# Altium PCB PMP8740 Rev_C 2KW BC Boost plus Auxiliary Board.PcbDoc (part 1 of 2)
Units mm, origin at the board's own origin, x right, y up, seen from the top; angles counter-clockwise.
Board outline 261.75 x 149.86 mm, 2 copper layers (Top Layer, Bottom Layer), stack 1.575 mm thick; 147 components, 79 nets, 365 pads, 168 vias.
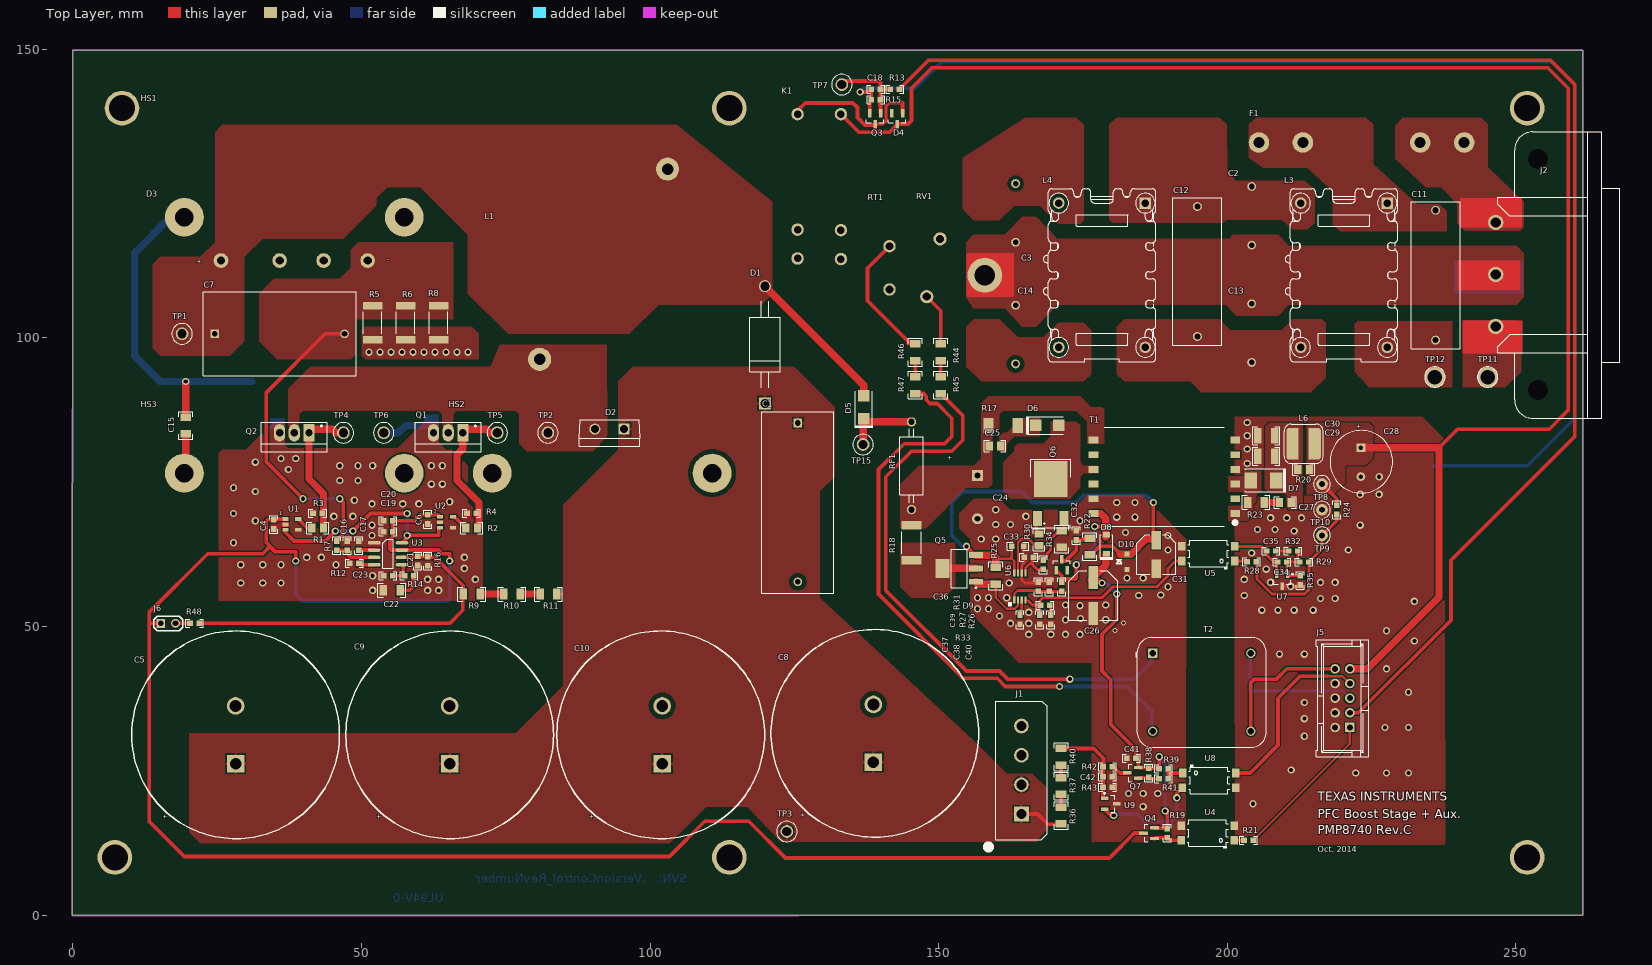
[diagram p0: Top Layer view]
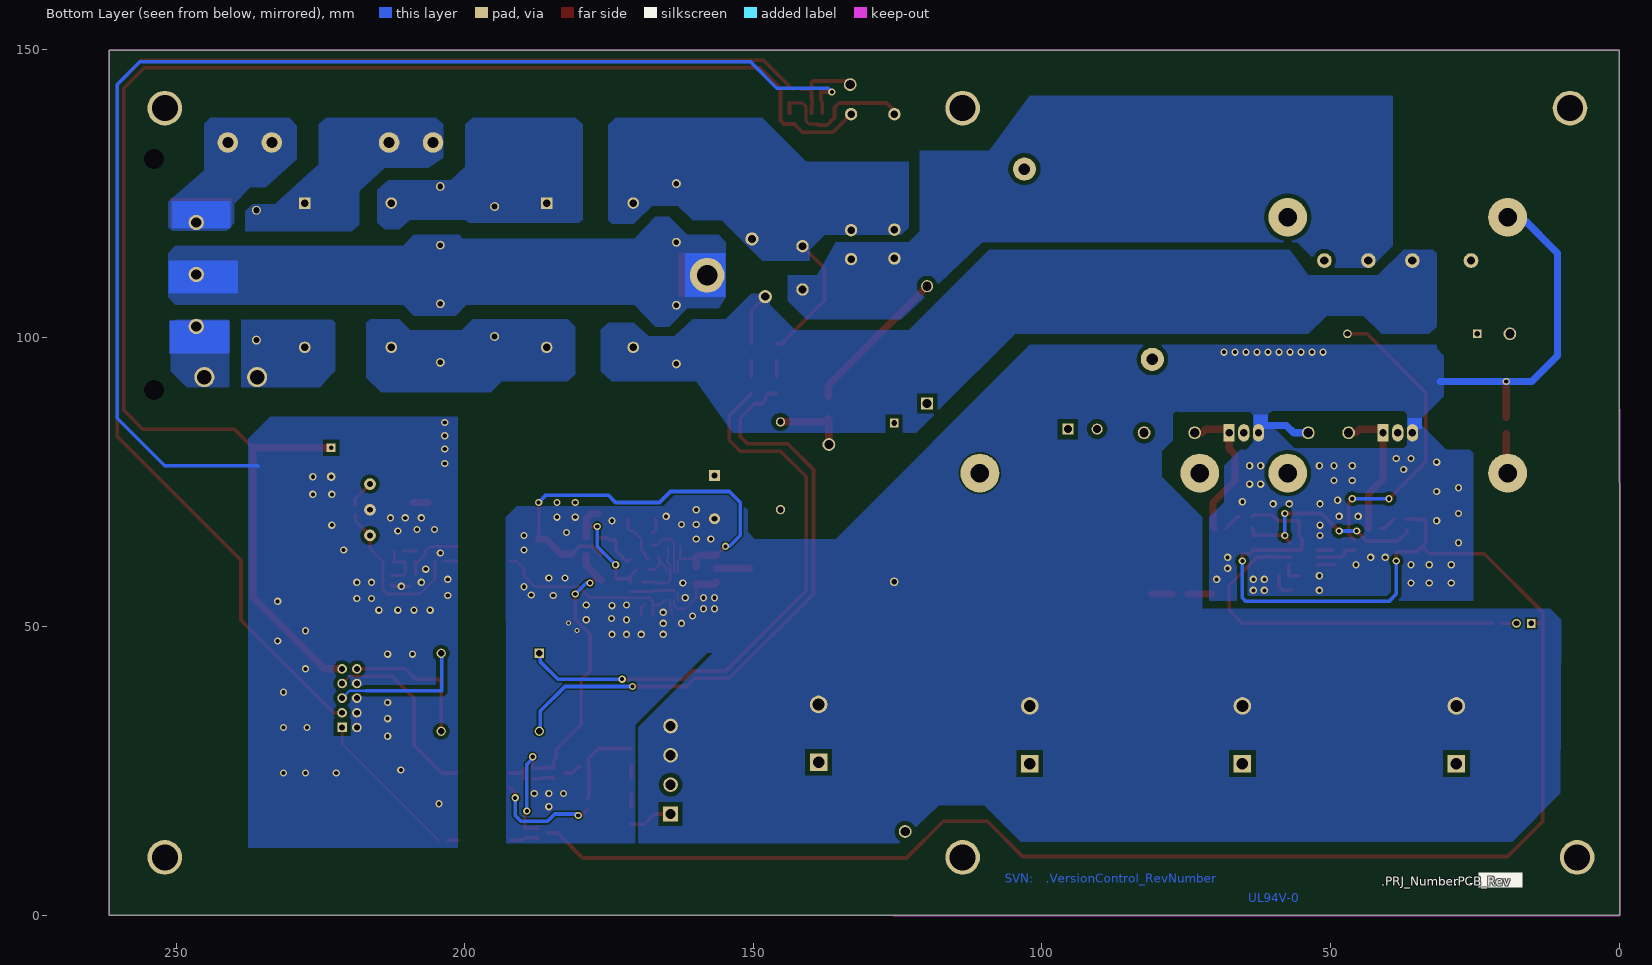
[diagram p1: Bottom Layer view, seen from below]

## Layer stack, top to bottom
Top Layer: signal copper 0.0356
Dielectric: core 1.5037, FR-4, Dk 4.8
Bottom Layer: signal copper 0.0356

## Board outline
-0.127,0 261.62,0 261.62,149.86 0,149.86

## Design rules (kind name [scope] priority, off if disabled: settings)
AcuteAngle [All] p1: minimum=4.50000000000000E+0001 checktracksonly=FALSE
AssemblyTestPointUsage [All] p1: valid=2
Clearance "Schematic Clearance Constraint_3" [InNet('NetD3_3')] p1: gap=0.762
Clearance "Schematic Clearance Constraint_2" [InNet('AC1')] p2: gap=0.762
Clearance Clearance_16 [InNamedPolygon('Bottom Layer-No Net 7')] p3: gap=0.254
Clearance "Schematic Clearance Constraint_1" [InNet('NetHS2_2')] p4: gap=0.762
Clearance "Schematic Clearance Constraint" [InNet('NetD2_2')] p5: gap=0.762
Clearance Clearance_15 [InNamedPolygon('Bottom Layer-No Net 7')] p6: gap=0.305
Clearance Clearance_14 [InNamedPolygon('Bottom Layer-No Net 9')] p7: gap=0.254
Clearance Clearance_13 [InNamedPolygon('Bottom Layer-No Net 9')] p8: gap=0.254
Clearance Clearance_12 [InNet('+390V')] p9: gap=0.762
Clearance Clearance_11 [InNamedPolygon('Top Layer-No Net 5')] p10: gap=0.762
Clearance Clearance_10 [InNamedPolygon('Top Layer-No Net 5')] p11: gap=0.762
Clearance Clearance_9 [InNamedPolygon('Top Layer-No Net 5')] p12: gap=0.508
Clearance Clearance_8 [InNamedPolygon('Top Layer-No Net 5')] p13: gap=0.508
Clearance Clearance_7 [InNamedPolygon('Top Layer-No Net 5')] p14: gap=0.508
Clearance Clearance_6 [InNamedPolygon('Bottom Layer-No Net 8')] p15: gap=0.254
Clearance Clearance_5 [InNamedPolygon('Top Layer-No Net 10')] p16: gap=0.254
Clearance Clearance_4 [InNamedPolygon('Top Layer-No Net 5')] p17: gap=0.762
Clearance Clearance_3 [InNamedPolygon('Bottom Layer-No Net 7')] p18: gap=0.254
Clearance Clearance_2 [InNamedPolygon('Bottom Layer-No Net 7')] p19: gap=0.254
Clearance Clearance_1 [InNamedPolygon('Top Layer-No Net 3')] p20: gap=0.254
Clearance Clearance_BoardEdge_MountingHoles [OnCopper and InComponentClass('Mounting Holes') vs IsKeepOut] p21: gap=1.016
Clearance Clearance_BoardEdge_Poly [OnCopper and InPoly vs IsKeepOut] p22: gap=0.635
Clearance Clearance_BoardEdge [OnCopper and Not InComponentClass('Logo') and not InComponentClass('FiducialMark') and not InRegion(1000,500,4000,800) and Not IsKeepout vs IsKeepOut] p23: gap=0.635
Clearance Clearance_Poly [InPolygon] p24: gap=0.635
Clearance [All] p25: gap=0.229
ComponentClearance ComponentClearance_Logo [InComponentClass('Logo')] p1: gap=1.27 collisioncheckmode=3 verticalgap=0.254 showdistances=FALSE
ComponentClearance ComponentClearance_ScrewToNut [(HasFootprint('NY PMS 440 0025 PH')) vs (HasFootprint('Keystone_1902C'))] p2: gap=0.127 collisioncheckmode=3 verticalgap=0.254 showdistances=FALSE
ComponentClearance ComponentClearance_MountingHoles [InComponentClass('Mounting Holes')] p3: gap=6.35 collisioncheckmode=3 verticalgap=2540 showdistances=FALSE
ComponentClearance ComponentClearance_SmallPassives [HasFootprint('0201*') or HasFootprint('0402*') or HasFootprint('0508') or HasFootprint('0603*') or HasFootprint('0612') or HasFootprint('0805*') or HasFootprint('0815*') or HasFootprint('0830*') or HasFootprint('1206*') or HasFootprint('1210*') or HasFootprint('1808*') or HasFootprint('1812*') or HasFootprint('1825*') or HasFootprint('2010*') or HasFootprint('2220*') or HasFootprint('2225*') or HasFootprint('2512*') or HasFootprint('2728*') or HasFootprint('3518*') vs HasFootprint('0201*') or HasFootprint('0402*') or HasFootprint('0508') or HasFootprint('0603*') or HasFootprint('0612') or HasFootprint('0805*') or HasFootprint('0815*') or HasFootprint('0830*') or HasFootprint('1206*') or HasFootprint('1210*') or HasFootprint('1808*') or HasFootprint('1812*') or HasFootprint('1825*') or HasFootprint('2010*') or HasFootprint('2220*') or HasFootprint('2225*') or HasFootprint('2512*') or HasFootprint('2728*') or HasFootprint('3518*')] p4: gap=0.508 collisioncheckmode=3 verticalgap=0.254 showdistances=FALSE
ComponentClearance ComponentClearance_THtoSMT [IsThruComponent vs IsSMTComponent] p5: gap=0.508 collisioncheckmode=3 verticalgap=0.762 showdistances=FALSE
ComponentClearance ComponentClearance_THtoTH [IsThruComponent vs IsThruComponent] p6: gap=3 collisioncheckmode=3 verticalgap=0.762 showdistances=FALSE
ComponentClearance [All] p7: gap=0.508 collisioncheckmode=3 verticalgap=2540 showdistances=FALSE
DiffPairsRouting [All] p1: maxlimit=2.54 minlimit=0.254 mostfreqgap=0.254 maxuncoupledlength=25.4
FabricationTestPointUsage TestPointUsage [All] p1: valid=2 allowmultiple=FALSE
FabricationTestpoint Testpoint [All] p1: side=3 testpointundercomponent=TRUE minsize=1.016 maxsize=2.54 preferedsize=1.524 minholesize=0 maxholesize=1.016 preferedholesize=0.813 testpointgrid=0.025 allowsidetop=TRUE allowsidebottom=TRUE usegrid=TRUE gridtolerance=0
FanoutControl Fanout_LCC [IsLCC] p1: bgadir=Out bgaviamode=Centered fanoutstyle=Auto fanoutdirection=Alternating viagrid=0.025 // Fanout_LCC (Default Rule)
FanoutControl Fanout_BGA [IsBGA] p2: bgadir=Out bgaviamode=Centered fanoutstyle=Auto fanoutdirection=Alternating viagrid=0.025 // Fanout_BGA (Default Rule)
FanoutControl Fanout_Default [All] p4: bgadir=Out bgaviamode=Centered fanoutstyle=Auto fanoutdirection=Alternating viagrid=0.025 // Fanout_Default (Default Rule)
FanoutControl Fanout_Small [(CompPinCount < 5)] p5: bgadir=Out bgaviamode=Centered fanoutstyle=Auto fanoutdirection=OutThenIn viagrid=0.025 // Fanout_Small (Default Rule)
Height [All] p1: minheight=0 maxheight=45 prefheight=12.7
HoleSize [All] p1: absolutevalues=TRUE maxlimit=6.375 minlimit=0.203 maxpercent=80.000 minpercent=20.000
MinimumAnnularRing MinimumAnnularRing_ThermalPadVias [IsVia and InAnyComponent] p1: minimumring=0.15
MinimumAnnularRing [All] p2: minimumring=0.229
MinimumSolderMaskSliver MinimumSolderMaskSliver_Logo [InComponentClass('Logo') vs InComponentClass('Logo')] p1: minsoldermaskwidth=0.018
MinimumSolderMaskSliver [All] p2: minsoldermaskwidth=0.1
PlaneConnect [All] p1: planeconnectstyle=Relief reliefexpansion=0.254 reliefentries=4 reliefconductorwidth=0.254 reliefairgap=0.254
PolygonConnect PolygonConnect_37 [All vs IsNamedPolygon('Bottom Layer-No Net 11')] p1: connectstyle=Direct reliefconductorwidth=0.254 reliefentries=4 polygonreliefangle="90 Angle" airgapwidth=0.254
PolygonConnect PolygonConnect_36 [All vs IsNamedPolygon('Bottom Layer-No Net 11')] p2: connectstyle=Direct reliefconductorwidth=0.254 reliefentries=4 polygonreliefangle="90 Angle" airgapwidth=0.254
PolygonConnect PolygonConnect_35 [All vs IsNamedPolygon('Top Layer-No Net 1')] p3: connectstyle=Direct reliefconductorwidth=0.254 reliefentries=4 polygonreliefangle="90 Angle" airgapwidth=0.254
PolygonConnect PolygonConnect_34 [All vs IsNamedPolygon('Top Layer-No Net 1')] p4: connectstyle=Direct reliefconductorwidth=0.254 reliefentries=4 polygonreliefangle="90 Angle" airgapwidth=0.254
PolygonConnect PolygonConnect_33 [All vs IsNamedPolygon('Bottom Layer-No Net 10')] p5: connectstyle=Direct reliefconductorwidth=0.254 reliefentries=4 polygonreliefangle="90 Angle" airgapwidth=0.254
PolygonConnect PolygonConnect_32 [All vs IsNamedPolygon('Bottom Layer-No Net 4')] p6: connectstyle=Direct reliefconductorwidth=0.254 reliefentries=4 polygonreliefangle="90 Angle" airgapwidth=0.254
PolygonConnect PolygonConnect_31 [All vs IsNamedPolygon('Bottom Layer-No Net 9')] p7: connectstyle=Direct reliefconductorwidth=0.254 reliefentries=4 polygonreliefangle="90 Angle" airgapwidth=0.254
PolygonConnect PolygonConnect_30 [All vs IsNamedPolygon('Top Layer-No Net 13')] p8: connectstyle=Direct reliefconductorwidth=0.254 reliefentries=4 polygonreliefangle="90 Angle" airgapwidth=0.254
PolygonConnect PolygonConnect_29 [All vs IsNamedPolygon('Top Layer-No Net 12')] p9: connectstyle=Direct reliefconductorwidth=0.254 reliefentries=4 polygonreliefangle="90 Angle" airgapwidth=0.254
PolygonConnect PolygonConnect_28 [All vs IsNamedPolygon('Top Layer-No Net 11')] p10: connectstyle=Direct reliefconductorwidth=0.254 reliefentries=4 polygonreliefangle="90 Angle" airgapwidth=0.254
PolygonConnect PolygonConnect_27 [All vs IsNamedPolygon('Bottom Layer-No Net 8')] p11: connectstyle=Direct reliefconductorwidth=0.254 reliefentries=4 polygonreliefangle="90 Angle" airgapwidth=0.254
PolygonConnect PolygonConnect_26 [All vs IsNamedPolygon('Top Layer-No Net 10')] p12: connectstyle=Direct reliefconductorwidth=0.254 reliefentries=4 polygonreliefangle="90 Angle" airgapwidth=0.254
PolygonConnect PolygonConnect_25 [All vs IsNamedPolygon('Top Layer-No Net 9')] p13: connectstyle=Direct reliefconductorwidth=0.254 reliefentries=4 polygonreliefangle="90 Angle" airgapwidth=0.254
PolygonConnect PolygonConnect_24 [All vs IsNamedPolygon('Top Layer-No Net 8')] p14: connectstyle=Direct reliefconductorwidth=0.254 reliefentries=4 polygonreliefangle="90 Angle" airgapwidth=0.254
PolygonConnect PolygonConnect_23 [All vs IsNamedPolygon('Top Layer-No Net 3')] p15: connectstyle=Direct reliefconductorwidth=0.254 reliefentries=4 polygonreliefangle="90 Angle" airgapwidth=0.254
PolygonConnect PolygonConnect_22 [All vs IsNamedPolygon('M5 Assembly Top-No Net')] p16: connectstyle=Direct reliefconductorwidth=0.254 reliefentries=4 polygonreliefangle="90 Angle" airgapwidth=0.254
PolygonConnect PolygonConnect_21 [All vs IsNamedPolygon('Top Layer-No Net 5')] p17: connectstyle=Relief reliefconductorwidth=0.508 reliefentries=4 polygonreliefangle="90 Angle" airgapwidth=0.254
PolygonConnect PolygonConnect_20 [All vs IsNamedPolygon('Top Layer-No Net 7')] p18: connectstyle=Direct reliefconductorwidth=0.254 reliefentries=4 polygonreliefangle="90 Angle" airgapwidth=0.254
PolygonConnect PolygonConnect_19 [All vs IsNamedPolygon('Top Layer-No Net 6')] p19: connectstyle=Direct reliefconductorwidth=0.254 reliefentries=4 polygonreliefangle="90 Angle" airgapwidth=0.254
PolygonConnect PolygonConnect_18 [All vs IsNamedPolygon('Bottom Layer-No Net 8')] p20: connectstyle=Relief reliefconductorwidth=0.508 reliefentries=4 polygonreliefangle="90 Angle" airgapwidth=0.254
PolygonConnect PolygonConnect_17 [All vs IsNamedPolygon('Top Layer-No Net 4')] p21: connectstyle=Direct reliefconductorwidth=0.254 reliefentries=4 polygonreliefangle="90 Angle" airgapwidth=0.254
PolygonConnect PolygonConnect_16 [All vs IsNamedPolygon('Bottom Layer-No Net 7')] p22: connectstyle=Direct reliefconductorwidth=0.254 reliefentries=4 polygonreliefangle="90 Angle" airgapwidth=0.254
PolygonConnect PolygonConnect_15 [All vs IsNamedPolygon('Top Layer-No Net 3')] p23: connectstyle=Direct reliefconductorwidth=0.254 reliefentries=4 polygonreliefangle="90 Angle" airgapwidth=0.254
PolygonConnect PolygonConnect_14 [All vs IsNamedPolygon('Bottom Layer-No Net 7')] p24: connectstyle=Direct reliefconductorwidth=0.254 reliefentries=4 polygonreliefangle="90 Angle" airgapwidth=0.254
PolygonConnect PolygonConnect_13 [All vs IsNamedPolygon('Bottom Layer-No Net 6')] p25: connectstyle=Direct reliefconductorwidth=0.254 reliefentries=4 polygonreliefangle="90 Angle" airgapwidth=0.254
PolygonConnect PolygonConnect_12 [All vs IsNamedPolygon('Bottom Layer-No Net 6')] p26: connectstyle=Direct reliefconductorwidth=0.254 reliefentries=4 polygonreliefangle="90 Angle" airgapwidth=0.254
PolygonConnect PolygonConnect_11 [All vs IsNamedPolygon('M1 Board Outline-No Net 1')] p27: connectstyle=Direct reliefconductorwidth=0.254 reliefentries=4 polygonreliefangle="90 Angle" airgapwidth=0.254
PolygonConnect PolygonConnect_10 [All vs IsNamedPolygon('M1 Board Outline-No Net 1')] p28: connectstyle=Direct reliefconductorwidth=0.254 reliefentries=4 polygonreliefangle="90 Angle" airgapwidth=0.254
PolygonConnect PolygonConnect_9 [All vs IsNamedPolygon('M1 Board Outline-No Net')] p29: connectstyle=Direct reliefconductorwidth=0.254 reliefentries=4 polygonreliefangle="90 Angle" airgapwidth=0.254
PolygonConnect PolygonConnect_8 [All vs IsNamedPolygon('Bottom Layer-No Net 5')] p30: connectstyle=Direct reliefconductorwidth=0.254 reliefentries=4 polygonreliefangle="90 Angle" airgapwidth=0.254
PolygonConnect PolygonConnect_7 [All vs IsNamedPolygon('Bottom Layer-No Net 4')] p31: connectstyle=Direct reliefconductorwidth=0.254 reliefentries=4 polygonreliefangle="90 Angle" airgapwidth=0.254
PolygonConnect PolygonConnect_6 [All vs IsNamedPolygon('Bottom Layer-No Net 3')] p32: connectstyle=Direct reliefconductorwidth=0.254 reliefentries=4 polygonreliefangle="90 Angle" airgapwidth=0.254
PolygonConnect PolygonConnect_5 [All vs IsNamedPolygon('Top Layer-No Net 2')] p33: connectstyle=Direct reliefconductorwidth=0.254 reliefentries=4 polygonreliefangle="90 Angle" airgapwidth=0.254
PolygonConnect PolygonConnect_4 [All vs IsNamedPolygon('Bottom Layer-No Net 2')] p34: connectstyle=Direct reliefconductorwidth=0.254 reliefentries=4 polygonreliefangle="90 Angle" airgapwidth=0.254
PolygonConnect PolygonConnect_3 [All vs IsNamedPolygon('Bottom Layer-No Net 1')] p35: connectstyle=Direct reliefconductorwidth=0.254 reliefentries=4 polygonreliefangle="90 Angle" airgapwidth=0.254
PolygonConnect PolygonConnect_2 [All vs IsNamedPolygon('Bottom Layer-No Net')] p36: connectstyle=Direct reliefconductorwidth=0.254 reliefentries=4 polygonreliefangle="90 Angle" airgapwidth=0.254
PolygonConnect PolygonConnect_1 [All vs IsNamedPolygon('Top Layer-No Net')] p37: connectstyle=Direct reliefconductorwidth=0.254 reliefentries=4 polygonreliefangle="90 Angle" airgapwidth=0.254
PolygonConnect [All] p38: connectstyle=Relief reliefconductorwidth=0.254 reliefentries=4 polygonreliefangle="90 Angle" airgapwidth=0.254
RoomDefinition "PMP8740 Rev_C 2KW BC Boost plus Auxiliary Schematic" [InComponentClass('PMP8740 Rev_C 2KW BC Boost plus Auxiliary Schematic')] p1: confinementstyle=ConfineIn formatcopy=TRUE lockcomponents=FALSE outline 242.773,1.676 356.565,1.676 356.565,57.556 242.773,57.556
RoutingVias ThermalPadVias [IsVia and InAnyComponent] p1: holewidth=0.2 width=0.5 viastyle="Through Hole" minholewidth=0.2 minwidth=0.5 maxholewidth=0.33 maxwidth=0.6
RoutingVias [All] p2: holewidth=0.406 width=0.864 viastyle="Through Hole" minholewidth=0.2 minwidth=0.66 maxholewidth=1.016 maxwidth=1.651
SMDToCorner [All] p1: distance=30000
SilkToSilkClearance [All] p1: silktosilkclearance=0.127
SilkscreenOverComponentPads [All] p1: minsilkscreentomaskgap=0.127
SolderMaskExpansion [All] p1: expansion=0.05
Width [All] p1: maxlimit=2.54 minlimit=0.152 preferedwidth=0.254 checkconnectedcopper=TRUE
13 further rules are at their usual default settings.

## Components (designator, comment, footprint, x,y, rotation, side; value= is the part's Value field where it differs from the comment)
C1 "R75PR4100AA30K" B32924_21.5mm 125.603,71.501 r270 top
C2 "C961U472MYWDBA7317" CAP_LEAD_394 204.221,116.078 r90 top
C3 "C961U472MYWDBA7317" CAP_LEAD_394 163.322,116.586 r90 top
C4 "C1608X7R1E105K080AB" 0603#1 34.798,67.691 r270 top
C5 "EET-ED2W331EA" CAP_381L_35MM 28.194,31.242 r90 top
C6 "C1608X7R1E105K080AB" 0603#1 61.468,68.58 r270 top
C7 "ECW-FA2J225J" B32923_29.5mm 35.819,100.711 r0 top
C8 "EET-ED2W331EA" CAP_381L_35MM 138.689,31.496 r90 top
C9 "EET-ED2W331EA" CAP_381L_35MM 65.278,31.242 r90 top locked
C10 "EET-ED2W331EA" CAP_381L_35MM 102.108,31.242 r90 top
C11 "ECQ-U2A474ML" CAPRR2250W80L2550T850H1750 236.093,110.871 r270 top
C12 "ECQ-U2A474ML" CAPRR2250W80L2550T850H1750 194.818,111.506 r270 top
C13 "C961U472MYWDBA7317" CAP_LEAD_394 204.216,95.758 r90 top
C14 "C961U472MYWDBA7317" CAP_LEAD_394 163.322,95.504 r90 top
C15 "CC1206KKX7RCBB102" 1206 19.558,84.836 r90 top
C16 "C1608C0G1H561J" 0603#1 47.498,64.008 r90 top
C17 "C1608C0G1H272J" 0603#1 49.53,64.008 r90 top
C18 "C1608X7R1H104K" 0603#1 139.11,143.081 r0 top
C19 "C1608X7R1H104K" 0603#1 54.618,66.421 r180 top
C20 "C1608X7R1E105K080AB" 0603#1 54.618,68.326 r180 top
C21 "C1608C0G1H821J" 0603#1 59.778,61.365 r270 top
C22 "GRM31CR71C335KA01L" 1206 55.253,56.261 r180 top
C23 "C1608X5R1A474K" 0603#1 54.618,58.801 r180 top
C24 "EKXG451ELL220ML20S" CAP_ZL-7.5X14.5MM 156.718,72.39 r0 top
C25 "C2012X7R2E102K" 0805_HV 159.766,81.28 r0 top
C26 "EEE-FK1E101P" SM_RADIAL_E 176.784,55.372 r270 top
C27 "C2012X7R2E102K" 0805_HV 210.058,71.501 r0 top
C28 "UHM1C102MPD" CAP_ALUM-10MM 223.144,81.026 r0 top
C29 "C3225X7R1E106M" 1210 206.756,79.502 r180 top
C30 "C3225X7R1E106M" 1210 206.756,83.058 r180 top
C31 "EEE-FK1H220P" SM_RADIAL_D 187.706,62.484 r270 top
C32 "C1608X7R1E105K080AB" 0603#1 173.863,65.786 r90 top
C33 "C1608X7R1H104K" 0603#2 163.703,63.881 r180 top
C34 "C1608C0G1H561J" 0603#1 209.509,61.18 r0 top
C35 "C1608X7R1H104K" 0603#1 207.604,63.085 r0 top
C36 "C1608C0G1H221J" 0603#1 165.608,61.976 r180 top
C37 "C1608X7R1C224K" 0603#1 164.089,51.181 r270 top
C38 "C1608C0G1H221J" 0603#1 167.513,51.181 r270 top
C39 "C1608C0G1H680J" 0603#1 167.264,56.896 r90 top
C40 "C1608X7R2A223K" 0603#1 169.418,51.181 r270 top
C41 "C1608X7R1E105K080AB" 0603#1 183.388,27.178 r180 top
C42 "C1608C0G1H272J" 0603#1 179.269,23.97 r0 top
D1 "1N5406" DO-201AD 119.888,98.806 r90 top
D2 "IDH10SG60C" TO-220-2 92.969,84.201 r180 top
D3 "D-BRIDGE_GSIB_20A_SERIES" BRIDGE-TSIL_PKG 38.359,113.411 r0 top
D4 "BAS21-7-F" SOT-23 142.793,138.001 r270 top
D5 "S1M-13-F" SMA 137.033,88.011 r90 top
D6 "MURA160T3G" SMA 168.783,84.836 r0 top
D7 "MBRS2H100T3G" SMB 206.248,75.311 r180 top
D8 "SMD110PL-TP" SOD-123FL 179.07,64.262 r90 top
D9 "BAS21-7-F" SOT-23 171.323,60.706 r90 top
D10 "D-MMSZ52XXBS_SERIES" SOD-323 182.626,61.214 r270 top
F1 "15A Fuse" FUSE_HOLDER_1/4 241.046,133.858 r180 top
HS1 "HEATSINK_780603B0200" HEATSINK_780603B0200 38.359,122.174 r180 top locked
HS2 "HEATSINK_780603B0200" HEATSINK_780603B0200 91.694,75.311 r0 top
HS3 "HEATSINK_780603B0200" HEATSINK_780603B0200 38.359,75.311 r0 top locked
J1 "0015244557" CONN_0015244557 164.338,25.146 r90 top
J2 "703W-00/54" CONN_QUALTEK-703W-0054 256.54,110.998 r270 top
J5 "5103308-1" CONN_5103308-1 219.964,37.592 r90 top
J6 "Test" HDR100_1X2 15.24,50.546 r0 top
K1 "ALZ51B12" RELAY_ALZ_FORM_A 129.413,127.381 r270 top
L1 "170.804 (SDR 15,0-0,21)" IND_TOR_1600MIL 91.948,106.426 r180 top
L3 "744825510" WE-CMB_XL 220.218,110.871 r270 top
L4 "744825510" WE-CMB_XL 178.308,110.871 r270 top
L6 "7447745022" WE-PD2-MS 213.233,81.661 r0 top
Q1 "IPP65R125C7" TO-220AB 65.024,83.566 r180 top
Q2 "IPP65R125C7" TO-220AB 38.354,83.566 r180 top
Q3 "BSS138" SOT-23 138.983,138.001 r270 top
Q4 "SI2319DS-T1-E3" SOT-23 186.441,14.224 r180 top
Q5 "BSP135" SOT-223 153.543,60.071 r180 top
Q6 "FCD4N60TM" DPAK 169.418,72.136 r90 top
Q7 "MMBT3906" SOT-23 183.642,24.63 r180 top
R1 "CRCW08052R21FKEA" 0805_HV 42.418,67.056 r0 top
R2 "CRCW08052R21FKEA" 0805_HV 69.088,67.056 r0 top
R3 "CRCW060310K0FKEA" 0603#1 42.418,69.596 r0 top
R4 "CRCW060310K0FKEA" 0603#1 69.088,69.596 r0 top
R5 "CSRN2512FK30L0" 2512 51.943,102.616 r270 top
R6 "CSRN2512FK30L0" 2512 57.658,102.616 r270 top
R7 "CRCW0603221RFKEA" 0603#1 45.72,64.008 r90 top
R8 "CSRN2512FK30L0" 2512 63.373,102.616 r270 top
R9 "CRCW1206332KFKEA" 1206 69.088,55.626 r180 top
R10 "CRCW1206332KFKEA" 1206 76.073,55.626 r180 top
R11 "CRCW1206309KFKEA" 1206 82.423,55.626 r0 top
R12 "CRCW060316K2FKEA" 0603#1 48.779,60.929 r0 top
R13 "CRCW060310K0FKEA" 0603#1 142.412,143.081 r0 top
R14 "CRCW060333K2FKEA" 0603#1 58.26,58.801 r180 top
R15 "CRCW0603100KFKEA" 0603#1 139.11,141.303 r0 top
R16 "CRCW060313K0FKEA" 0603#1 61.468,61.341 r90 top
R17 "STD" R2010 161.163,84.836 r0 top
R18 "CRCW251210K0FKEGHP" 2512M 145.288,64.516 r90 top
R19 "CRCW060347K5FKEA" 0603#1 189.616,14.224 r90 top
R20 "CRCW08052R21FKEA" 0805_HV 213.233,77.216 r0 top
R21 "CRCW060310K0FKEA" 0603#1 203.708,12.954 r180 top
R22 "CRCW1206100RFKEA" 1206 176.214,63.881 r90 top
R23 "CRCW1206100RFKEA" 1206 204.978,71.501 r0 top
R24 "CRCW060349R9FKEA" 0603#1 218.948,70.231 r270 top
R25 "CRCW120610M0JNEA" 1206 159.893,58.801 r90 top
R26 "CRCW060323K2FKEA" 0603#1 171.323,56.896 r90 top
R27 "CRCW06036K34FKEA" 0603#1 169.169,56.896 r270 top
R28 "CRCW060310K0FKEA" 0603#1 204.216,61.214 r0 top
R29 "CRCW060386K6FKEA" 0603#1 213.319,61.18 r0 top
R30 "CRCW08052R21FKEA" 0805_HV 167.386,65.024 r90 top
R31 "CRCW06037K50FKEA" 0603#1 168.148,60.706 r90 top
R32 "CRCW06037K50FKEA" 0603#1 211.414,63.085 r0 top
R33 "CRCW060316K2FKEA" 0603#1 168.437,53.688 r180 top
R34 "CRCW12061R00FKEA" 1206 171.323,65.151 r90 top
R35 "CRCW060310K0FKEA" 0603#1 212.684,58.005 r270 top
R36 "CRCW1206698KFKEA" 1206 171.196,17.272 r270 top
R37 "CRCW1206715KFKEA" 1206 171.196,22.352 r270 top
R38 "CRCW060347K5FKEA" 0603#1 186.436,24.63 r90 top
R39 "CRCW06038K25FKEA" 0603#1 188.976,25.392 r180 top
R40 "CRCW1206715KFKEA" 1206 171.196,27.432 r270 top
R41 "CRCW0603100KFKEA" 0603#1 188.976,23.614 r180 top
R42 "CRCW0603909KFKEA" 0603#1 179.269,25.748 r0 top
R43 "CRCW06036K81FKEA" 0603#1 179.269,22.192 r180 top
R44 "CRCW1206750KFKEA" 1206 150.368,97.536 r90 top
R45 "CRCW1206750KFKEA" 1206 150.368,91.821 r90 top
R46 "CRCW1206750KFKEA" 1206 145.923,97.536 r90 top
R47 "CRCW1206750KFKEA" 1206 145.923,91.821 r90 top
R48 "CRCW0603100KFKEA" 0603#1 21.082,50.546 r0 top
RF1 "EMC2-22RKI" EMC2 145.288,77.851 r90 top
RT1 "B57464S100M" DISK-7X21MM 141.478,112.141 r270 top
RV1 "SIOV-S20K275" DISK-846 149.098,112.141 r270 top
T1 "TBD" Wurth_760871113 189.103,75.946 r180 top
T2 "PA3000NL" PULSE_PA3000NL 195.58,38.608 r0 top
TP1 "5008" Keystone5008#1 18.923,100.711 r0 top
TP2 "5008" Keystone5008#1 82.296,83.566 r0 top
TP3 "5005" Keystone5005 123.698,14.478 r0 top
TP4 "5122" Keystone5122 46.863,83.566 r0 top
TP5 "5122" Keystone5122 73.533,83.566 r0 top
TP6 "5006" Keystone5006 53.848,83.566 r0 top
TP7 "5122" Keystone5122 133.223,143.891 r0 top
TP8 "5000" Keystone5000 216.408,74.676 r0 top
TP9 "5004" Keystone5004 216.408,65.786 r0 top
TP10 "5001" Keystone5001 216.408,70.231 r0 top
TP11 "5008" Keystone5008#2 245.11,93.218 r0 top
TP12 "5008" Keystone5008#2 235.966,93.218 r0 top
TP15 "5008" Keystone5008#1 136.906,81.534 r0 top
U1 "UCC27517DBV" SOT23-5P 37.973,67.691 r0 top
U2 "UCC27517DBV" SOT23-5P 64.77,68.072 r0 top
U3 "UCC28180D" D0008A_N 54.618,62.611 r0 top
U4 "FOD817DS" N04C 196.601,14.224 r180 top
U5 "FOD817DS" N04C 196.723,62.611 r180 top
U6 "LM5023MM" DGK8 164.089,56.896 r90 top
U7 "LMV431AIMF" MF03A_N 209.509,58.005 r270 top
U8 "FOD817DS" N04C 196.85,23.368 r0 top
U9 "LMV431AIMF" MF03A_N 179.782,19.296 r0 top

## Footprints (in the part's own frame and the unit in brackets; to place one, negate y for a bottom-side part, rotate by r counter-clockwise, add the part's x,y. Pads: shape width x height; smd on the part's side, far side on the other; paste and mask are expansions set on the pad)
0603#1 [mm] "0603 from SM-752 data"
  rect 1x0.95 smd: 1(-0.8,0) 2(0.8,0)
  silkscreen extent -1.52,-0.69 1.52,0.69, body extent -0.87,-0.47 0.87,0.47, height 0.85
0603#2 [mm] "0603 from SM-752 data"
  rect 1x0.95 smd: 1(-1.054,0) 2(1.054,0)
  silkscreen extent -1.91,-0.69 1.81,0.69, body extent -0.87,-0.47 0.87,0.47, height 0.85
0805_HV [mil] "0805 with 30mil clearance between pads"
  rect 50x63 smd: 1(-40,0) 2(40,0)
  silkscreen extent -74,-40 74,40, body extent -43,-29 43,29, height 43
1206 [mm] "1206 from SM-752 data"
  rect 1.3x1.85 smd: 1(-1.45,0) 2(1.45,0)
  silkscreen extent -2.4,-1.21 2.4,1.21, body extent -1.7,-0.9 1.7,0.9, height 1.35
1210 [mm] "1210 from SM-752 data"
  rect 1.3x2.7 smd: 1(-1.45,0) 2(1.45,0)
  silkscreen extent -2.32,-1.57 2.32,1.57, body extent -1.7,-1.35 1.7,1.35, height 1.35
2512 [mm] "Chip Resistor, Body 6.3x3.2mm, IPC Medium Density"
  rect 1.3x3.4 smd: 1(-2.95,0) 2(2.95,0)
  silkscreen extent -1.9,-1.6 1.9,1.6, body extent -3.22,-1.67 3.22,1.67, height 0.71
2512M [mm] "Chip Resistor, Body 6.3x3.2mm, IPC Low Density"
  rect 1.5x3.5 smd: 1(-3.05,0) 2(3.05,0)
  silkscreen extent -1.9,-1.65 1.9,1.65, body extent -3.22,-1.67 3.22,1.67, height 0.71
B32923_29.5mm [mm] "Epcos film capacitors, 22.5mm spacing"
  rect 1.5x1.5 hole 1: 1(-11.25,0)
  round 1.5 hole 1: 2(11.25,0)
  silkscreen extent -13.25,-7.25 13.25,7.25, body extent -13.25,-7.25 13.25,7.25, height 29.5
B32924_21.5mm [mm] "Epcos film capacitors, 27.5mm spacing"
  rect 1.5x1.5 hole 1: 1(-13.75,0)
  round 1.5 hole 1: 2(13.75,0)
  silkscreen extent -15.75,-6.25 15.75,6.25, body extent -15.75,-6.25 15.75,6.25, height 21.5
BRIDGE-TSIL_PKG [mil]
  round 100 hole 57: 1(-500,0) 2(-100,0) 3(200,0) 4(500,0)
CAP_381L_35MM [mil]
  rect 120x120 hole 79 mask+5: 1(-197,0)
  round 120 hole 81 mask+5: 2(197,0)
CAP_ALUM-10MM [mil]
  rect 60x60 hole 31: 1(0,-2)
  round 60 hole 31: 2(0,-199)
CAP_LEAD_394 [mil]
  round 60 hole 38: 1(0,0) 2(400,0)
CAP_ZL-7.5X14.5MM [mil]
  rect 75x75 hole 40: 1(0,149)
  round 75 hole 40: 2(0,-146)
CAPRR2250W80L2550T850H1750 [mm] "PANASONIC"
  round 1.55 hole 1.05: 1(-11.25,0) 2(11.25,0)
  silkscreen extent -12.75,-4.25 12.75,4.25, body extent -12.75,-4.25 12.75,4.25, height 17.5
CONN_5103308-1 [mm] "TE Connectivity (AMP) Rev E datasheet"
  rect 1.65x1.65 hole 1.016 mask+0: 1(-5.08,-1.27)
  round 1.65 hole 1.016 mask+0: 2(-5.08,1.27) 3(-2.54,-1.27) 4(-2.54,1.27) 5(0,-1.27) 6(0,1.27) 7(2.54,-1.27) 8(2.54,1.27) 9(5.08,-1.27) 10(5.08,1.27)
  silkscreen extent -10.16,-4.57 10.16,4.57, body extent -10.16,-4.57 10.16,4.57, height 9.87
CONN_0015244557 [mil] "Molex"
  rect 100x100 hole 70: 1(-300,0)
  round 100 hole 70: 2(-100,0) 3(100,0) 4(300,0)
  silkscreen extent -543,-175 470,243, body extent -461,-163 461,163, height 404
CONN_QUALTEK-703W-0054 [mil] "AC Receptacle"
  round 105 hole 70: 1(354.33,-395) 2(-354.33,-395) 3(0,-395)
  round 39.37 hole 137.8 unplated: MH1(-787.4,-107.36) MH2(787.4,-107.36)
  silkscreen extent -972,-380 981,452, body extent -972,-477 981,452, height 1130
D0008A_N [mm] "SOIC, 8-Leads, Body 4.9x3.9mm, Pitch 1.27mm, IPC Medium Density"
  oval 2.2x0.6 smd: 1(-2.4,1.905) 2(-2.4,0.635) 3(-2.4,-0.635) 4(-2.4,-1.905) 5(2.4,-1.905) 6(2.4,-0.635) 7(2.4,0.635) 8(2.4,1.905)
  silkscreen extent -0.9,-2.5 0.9,2.5, body extent -3,-2.45 3,2.45, height 1.63
DGK8 [mil]
  rect 50x15 smd: 1(-90.2,39) 2(-90.2,13.4) 3(-90.2,-12.2) 4(-90.2,-37.8) 5(93.4,-37.8) 6(93.4,-12.2) 7(93.4,13.4) 8(93.4,39)
  silkscreen extent -132,57 -107,82
DISK-7X21MM [mil]
  round 85 hole 52: 1(-147.64,0) 2(147.64,0)
DISK-846 [mil]
  round 90 hole 55: 1(-197.5,45) 2(196.5,-46)
DO-201AD [mm] "Vishay dimensions"
  rect 2.1x2.1 hole 1.6: 1(-10.16,0)
  round 2.1 hole 1.6: 2(10.16,0)
  silkscreen extent -7.47,-2.7 7.57,2.61, body extent -10.82,-2.68 10.82,2.61, height 5.3
DPAK [mm] "D-PAK, 3-Pads, Body 6.22x6.73mm (max), TO-252AA using nominal STEP model"
  rect 2.6x1.6 smd: 1(-3.4,2.28) 3(-3.4,-2.28)
  rect 6.2x5.8 smd paste-2.9: 4(3.4,0)
  silkscreen extent -5,-3.5 6.83,3.5, body extent -3.86,-3.29 5.84,3.29, height 2.48
EMC2 [mm] "Welwyn"
  round 1.6 hole 1.1: 1(-7.6,0) 2(7.6,0)
  silkscreen extent -6.42,-2 6.42,2, body extent -8.02,-2 8.02,2, height 3.98
FUSE_HOLDER_1/4 [mil]
  round 140 hole 75: 1(0,0) 2(300,0) 3(1100,0) 4(1400,0)
HDR100_1X2 [mil]
  rect 60x60 hole 38: 1(0,0)
  round 60 hole 38: 2(100,0)
  silkscreen extent -50,-50 150,50
HEATSINK_780603B0200 [mil]
  round 265 hole 125: 1(-750,50) 2(750,50)
IND_TOR_1600MIL [mm]
  round 4 hole 2: 1(-11.08,-22.83) 2(11.08,10.13)
Keystone5000 [mil] "For Keystone 500x miniature loop terminals"
  round 80 hole 40: 1(0,0)
  silkscreen extent -58,-58 58,58, body extent -49,-49 49,49, height 182
Keystone5001 [mil] "For Keystone 500x miniature loop terminals"
  round 80 hole 40: 1(0,0)
  silkscreen extent -58,-58 58,58, body extent -49,-49 49,49, height 182
Keystone5004 [mil] "For Keystone 500x miniature loop terminals"
  round 80 hole 40: 1(0,0)
  silkscreen extent -58,-58 58,58, body extent -49,-49 49,49, height 182
Keystone5005 [mil] "Keystone Compact loops"
  round 87 hole 63: 1(0,0)
  silkscreen extent -70,-70 70,70, body extent -63,-63 62,63, height 225
Keystone5006 [mil] "Keystone Compact loops"
  round 87 hole 63: 1(0,0)
  silkscreen extent -70,-70 70,70, body extent -63,-63 62,63, height 225
Keystone5008#1 [mil] "Keystone Compact loops"
  round 87 hole 63: 1(0,0)
  silkscreen extent -70,-70 70,70, body extent -63,-63 62,63, height 225
Keystone5008#2 [mil] "Keystone Compact loops"
  round 137.8 hole 98.43: 1(0,0)
  silkscreen extent -70,-70 70,70, body extent -63,-63 62,63, height 225
Keystone5122 [mil] "Keystone Compact loops"
  round 87 hole 63: 1(0,0)
  silkscreen extent -70,-70 70,70, body extent -63,-63 62,63, height 225
MF03A_N [mm] "SOT23, 3-Leads, Body 2.9x1.3mm, Pitch 0.95mm, Lead Span 2.4mm, IPC Medium Density"
  rect 1.3x0.6 smd: 1(-1.05,0.95) 2(-1.05,-0.95) 3(1.05,0)
  silkscreen extent -1.17,-1.5 0.7,1.93, body extent -0.7,-1.5 0.7,1.5, height 1.12
N04C [mm] "FAIRCHILD"
  rect 1.3x1.5 smd mask+0.065: 1(-4.587,1.27) 2(-4.612,-1.27) 3(4.588,-1.27) 4(4.613,1.27)
  silkscreen extent -3.56,-2.3 3.56,2.72, body extent -5.08,-2.3 5.08,2.3, height 3.87
PULSE_PA3000NL [mm] "TH, 4-Leads, Body 19x22.3mm"
  rect 1.6x1.6 hole 1.07: 1(-8.5,6.75)
  round 1.6 hole 1.07: 2(-8.5,-6.75) 3(8.5,-6.75) 4(8.5,6.75)
  silkscreen extent -11.5,-9.5 11.15,9.5, body extent -11.16,-9.51 11.16,9.51, height 12.65
R2010 [mil]
  rect 70x102 smd: 1(-100,0) 2(100,0)
RELAY_ALZ_FORM_A [mil]
  round 85 hole 51: 1(-448,-152) 2(339,-152) 3(536,-152) 4(540,144) 5(343,144) 6(-448,144)
SM_RADIAL_D [mm] "6.3 x 5.8mm:  Panasonic D"
  rect 3.2x1.6 smd: 1(-2.5,0) 2(2.5,0)
  silkscreen extent -3.4,-3.4 3.4,3.4, body extent -3.41,-3.41 3.41,3.41, height 6.1
SM_RADIAL_E [mm] "8 x 6.2mm:  Panasonic E"
  rect 4x1.6 smd: 1(-3.1,0) 2(3.1,0)
  silkscreen extent -4.25,-4.25 4.25,4.25, body extent -4.26,-4.26 4.26,4.26, height 6.5
SMA [mm] "Molded Diode, 2-Leads, Body 4.3x2.6mm, IPC Medium Density, based on OnSemi component dimensions and land pattern"
  rect 2x2 smd: 1(-2,0) 2(2,0)
  silkscreen extent -3.66,-1.57 2.79,1.57, body extent -2.6,-1.3 2.6,1.3, height 2.42
SMB [mm] "Molded Diode, 2-Leads, Body 5.4x3.6mm, IPC Medium Density, based on OnSemi component dimensions"
  rect 2.159x2.743 smd: 1(-2.21,0) 2(2.21,0)
  silkscreen extent -3.94,-2.08 3.18,2.08, body extent -2.7,-1.8 2.7,1.8, height 2.32
SOD-123FL [mm] "Copied from SOD-123"
  rect 0.915x1.22 smd: 1(-1.637,0) 2(1.637,0)
  silkscreen extent -2.74,-1.16 1.68,1.16, body extent -1.9,-0.9 1.9,0.9, height 1
SOD-323 [mil]
  rect 35x35 smd mask+5: 1(-52.5,0) 2(52.5,0)
  silkscreen extent -15,-74 15,-34
SOT23-5P [mil]
  rect 42x25 smd: 1(-45,37) 2(-45,0) 3(-45,-37) 4(42,-37) 5(42,37)
SOT-23 [mm] "SOT23, 3-Leads, Body 2.9x1.3mm, Pitch 0.95mm, Lead Span 2.5mm, IPC Medium Density"
  rect 1.5x0.6 smd: 1(-0.95,0.95) 2(-0.95,-0.95) 3(0.95,0)
  silkscreen extent 0.2,-1.5 0.7,1.5, body extent -1.16,-1.45 1.21,1.45, height 1
SOT-223 [mm] "SOT223/SC73, 4-Leads, Body 6.5x3.5mm, Pitch 2.3mm, Lead Span 7mm, IPC Medium Density"
  rect 2.4x1 smd: 1(-2.9,2.3) 2(-2.9,0) 3(-2.9,-2.3)
  rect 2.4x3.3 smd: 4(2.9,0)
  silkscreen extent -3.03,-3.35 1.4,3.47, body extent -3.5,-3.25 3.5,3.25, height 1.62
TO-220-2 [mm] "CREE"
  rect 1.9x1.9 hole 1.4: 1(-2.54,0)
  round 1.9 hole 1.4: 2(2.54,0)
  silkscreen extent -5.25,-1.64 5.26,3.01, body extent -5.21,-1.57 5.21,3.12, height 19.47
TO-220AB [mm] "Copied from Altium's version of TO3B"
  rect 1.93x3 hole 1.27: 1(-2.54,0)
  oval 1.93x3 hole 1.27: 2(0,0) 3(2.54,0)
  silkscreen extent -5.72,-1.85 5.71,3.3, body extent -5.61,-1.49 5.61,3.2, height 19.42
WE-CMB_XL [mm] "Wurth"
  rect 2x2 hole 1.3: 1(-12.5,7.5)
  round 2 hole 1.3: 6(12.5,7.5) 7(12.5,-7.5) 12(-12.5,-7.5)
  silkscreen extent -15,-10.18 15,9.3, body extent -15.25,-10.5 15.25,10.5, height 35
WE-PD2-MS [mm] "Wurth Elektronik recommended land pattern"
  rrect50% 2.15x5.5 smd: 1(-1.925,0) 2(1.925,0)
  rect 0.55x0.525 smd: 1(-1.13,-2.49) 1(-1.13,2.49) 2(1.12,-2.49) 2(1.13,2.49)
  silkscreen extent -3.4,-3.4 3.4,3.4, body extent -3.01,-2.6 3.01,2.6, height 2.3
Wurth_760871113 [mm] "Wurth Electronics Inc"
  rect 1.7x1.17 smd: 1(-12.265,6.35) 2(-12.265,3.81) 3(-12.265,1.27) 4(-12.265,-1.27) 5(-12.265,-3.81) 6(-12.265,-6.35) 7(12.265,-6.35) 8(12.265,-3.81) 9(12.265,-1.27) 10(12.265,1.27) 11(12.265,3.81) 12(12.265,6.35)
  silkscreen extent -12.55,-8.6 10.4,8.6, body extent -10.45,-8.65 10.45,8.65, height 14.01

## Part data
C1: library part B32924C3155M, "CAP, Polypropilene, 1uF, 630V, +/-20%, TH"
C2 C3 C13 C14: library part CAP_ECKANA_10MM, "Capacitor, Ceramic Disk X1Y2, 250Vac"
C4 C6 C20 C32 C41: "CAP, CERM, 1uF, 25V, +/-10%, X7R, 0603"
C5 C8 C9 C10: library part CAP_381L_35MM, "Capacitor, Electrolytic, Snap in., 330uF, 450Vdc, 105C, 20%"
C7: library part B32923C3225M, "CAP, Film Polyprop., 2.2uF, 630Vdc, 6Arms @ 200KHz, 20%, TH"
C11 C12: "CAP, Film, 0.47uF, 275V, +/-20%, TH"
C15: "CAP, CERM, 1000pF, 1000V, +/-10%, X7R, 1206"
C16 C34: "CAP, CERM, 560pF, 50V, +/-5%, C0G/NP0, 0603"
C17 C42: "CAP, CERM, 2700pF, 50V, +/-5%, C0G/NP0, 0603"
C18 C19 C33 C35: "CAP, CERM, 0.1uF, 50V, +/-10%, X7R, 0603"
C21: "CAP, CERM, 820pF, 50V, +/-5%, C0G/NP0, 0603"
C22: "CAP, CERM, 3.3uF, 16V, +/-10%, X7R, 1206"
C23: "CAP, CERM, 0.47uF, 10V, +/-10%, X5R, 0603"
C24: library part CAP_ZL_16MM_SERIES, "Capacitor, Electrolytic, 105C, 20%"
C25 C27: "CAP, CERM, 1000pF, 250V, +/-10%, X7R, 0805"
C26: "CAP, AL, 100uF, 25V, +/-20%, 0.26 ohm, SMD"
C28: library part CAP_EKZE_10MM_SERIES, "Capacitor, Alum Electrolytic 16 V, 105C, ±20%"
C29 C30: "CAP, CERM, 10uF, 25V, +/-20%, X7R, 1210"
C31: "CAP, AL, 22uF, 50V, +/-20%, 0.88 ohm, SMD"
C36 C38: "CAP, CERM, 220pF, 50V, +/-5%, C0G/NP0, 0603"
C37: "CAP, CERM, 0.22uF, 16V, +/-10%, X7R, 0603"
C39: "CAP, CERM, 68pF, 50V, +/-5%, C0G/NP0, 0603"
C40: "CAP, CERM, 0.022uF, 100V, +/-10%, X7R, 0603"
D1: "Diode, Switching-Bridge, 600V, 3A, TH"
D2: library part C3D08060A, "Diode, Schottky, 600V, 10A, TH"
D3: "Diode, Single-Phase In-Line Bridge Rectifier, 20A, 600V"
D4 D9: "Diode, Switching, 200V, 0.2A, SOT-23"
D5: library part US1M-13-F, "Diode, Standard, 1000V, 1A, SMA"
D6: "Diode, Ultrafast, 600V, 1A, SMA"
D7: library part MBRS260T3G, "Diode, Schottky, 100V, 2A, SMB"
D8: library part MBR1H100SFT3G, "Diode, Schottky, 100V, 1A, SOD-123FL"
D10: "Diode, Zener, 13V, 9.5-mA, 200mW"
F1: library part FUSEHOLDER_1/4BM, "Fuseholder, 1/4\" fuses, board mount + 15A Fuse"
HS1 HS2 HS3: "Heatsink,  Vertical-mount"
J1: "Header, 4POS, 200mil, Vertical, Tin, TH"
J2: "AC Receptacle, 10A 250VAC"
J5: "Header (shrouded), 100mil, 5x2, Gold, TH"
J6: library part HEADER_1X2, "Header, Male 2-pin, 100mil spacing,"
K1: library part RELAY_ALZ_SERIES, "Relay, SPST, 12V Coil Rating, Contact Rating 16A 250VAC"
L1: library part IND_D-TOROID, "Inductor, PFC Choke, 210uH 15A"
L3 L4: "Coupled inductor, 1mH, 12A, 0.009 ohm, TH"
L6: "Inductor, Drum Core, Ferrite, 2.2uH, 3.5A, 0.03 ohm, SMD"
Q1 Q2: library part IPP50R199CP, "MOSFET, N-CH, 650V, 18A, TO-220AB"
Q3: "MOSFET, N-CH, 50V, 0.22A, SOT-23"
Q4: "MOSFET, P-CH, -40V, -2.3A, SOT-23"
Q5: library part ZXMN10A11G, "MOSFET, N-CH, Depletion Mode, 600V, 20mA, SOT-223"
Q6: "MOSFET, N-CH, 600V, 3.9A, DPAK"
Q7: library part "MMBT3906, Fairchild Semiconductor", "Transistor, PNP, 40V, 0.2A, SOT-23"
R1 R2 R20 R30: "RES, 2.21 ohm, 1%, 0.125W, 0805"
R3 R4 R13 R21 R28 R35: "RES, 10.0k ohm, 1%, 0.1W, 0603"
R5 R6 R8: "RES, 0.03 ohm, 1%, 2W, 2512"
R7: "RES, 221 ohm, 1%, 0.1W, 0603"
R9 R10: "RES, 332k ohm, 1%, 0.25W, 1206"
R11: "RES, 309k ohm, 1%, 0.25W, 1206"
R12 R33: "RES, 16.2k ohm, 1%, 0.1W, 0603"
R14: "RES, 33.2k ohm, 1%, 0.1W, 0603"
R15 R41 R48: "RES, 100k ohm, 1%, 0.1W, 0603"
R16: "RES, 13.0k ohm, 1%, 0.1W, 0603"
R17: library part R2010_5%, "Resistor, Chip, 0.6W, 1%"
R18: library part CRCW25121K10JNEG, "RES, 10.0k ohm, 1%, 1W, 2512"
R19 R38: "RES, 47.5k ohm, 1%, 0.1W, 0603"
R22 R23: "RES, 100 ohm, 1%, 0.25W, 1206"
R24: "RES, 49.9 ohm, 1%, 0.1W, 0603"
R25: "RES, 10Meg ohm, 5%, 0.25W, 1206"
R26: "RES, 23.2k ohm, 1%, 0.1W, 0603"
R27: "RES, 6.34k ohm, 1%, 0.1W, 0603"
R29: "RES, 86.6k ohm, 1%, 0.1W, 0603"
R31 R32: "RES, 7.50k ohm, 1%, 0.1W, 0603"
R34: "RES, 1.00 ohm, 1%, 0.25W, 1206"
R36: "RES, 698k ohm, 1%, 0.25W, 1206"
R37 R40: "RES, 715k ohm, 1%, 0.25W, 1206"
R39: "RES, 8.25k ohm, 1%, 0.1W, 0603"
R42: "RES, 909k ohm, 1%, 0.1W, 0603"
R43: "RES, 6.81k ohm, 1%, 0.1W, 0603"
R44 R45 R46 R47: "RES, 750k ohm, 1%, 0.25W, 1206"
RF1: "RES, 22 ohm, 10%, 2W, Fusible, TH"
RT1: library part THERMISTOR-B57364_SERIES, "Thermistor, 10 Ohms, ±20%"
RV1: library part VARISTOR_SIOV-S20K275, "Varistor,  Disk, 350V, 1W, TA @ 85C°"
T1: library part 760871113, "Transformer, 1.31mH, SMT"
T2: "Transformer, 4 H, TH"
TP1 TP2 TP11 TP12 TP15: "Test Point, Compact, Orange, TH"
TP3: "Test Point, Compact, Red, TH"
TP4 TP5 TP7: "Test Point, Compact, Blue, TH"
TP6: "Test Point, Compact, Black, TH"
TP8: "Test Point, Miniature, Red, TH"
TP9: "Test Point, Miniature, Yellow, TH"
TP10: "Test Point, Miniature, Black, TH"
U1 U2: "IC, 4A Single Channel High-Speed Low-Side Gate Drivers"
U3: "8-PIN CONTINUOUS CONDUCTION MODE (CCM) PFC CONTROLLER, D0008A"
U4 U5 U8: "Optocoupler, 5kV RMS, SMT"
U6: "IC, AC-DC Quasi-Resonant Current Mode PWM Controller"
U7 U9: "Low-Voltage (1.24V) Adjustable Precision Shunt Regulator, 3-pin SOT-23"

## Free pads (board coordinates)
  round 6 hole 4.5: 0(7.27,10) 0(8.508,139.8) 0(113.728,10) 0(113.728,139.8) 0(251.968,10) 0(251.968,139.8)
  round 6 hole 3.5: 0(157.988,110.858)

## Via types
v1: diameter 1.27, hole 0.711, Top Layer to Bottom Layer, tented top, 131 vias
v2: diameter 1.27, hole 0.711, Top Layer to Bottom Layer, 35 vias
v3: diameter 0.889, hole 0.508, Top Layer to Bottom Layer, tented top, 2 vias

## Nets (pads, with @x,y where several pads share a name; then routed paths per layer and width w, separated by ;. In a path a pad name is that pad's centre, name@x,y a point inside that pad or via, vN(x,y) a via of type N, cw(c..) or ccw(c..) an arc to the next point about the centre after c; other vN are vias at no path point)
+390V: C1.1 C5.1 C8.1 C9.1 C10.1 D1.1 D2.1 J1.1 J1.2 R11.2 R36.2 TP3.1 | length 7.6
  Top Layer w0.635: J1.1@164.338,17.526 167.132,17.526 168.91,15.748 171.122,15.748 R36.2@171.196,15.822
AC1: C14.1 D3.2 L4.7 R44.2 RV1.2 | length 9.2
  Top Layer w0.635: RV1.2@147.93,107.15 150.368,104.712 R44.2@150.368,98.986
AC2: C3.2 K1.2 K1.5 L4.12 R46.2 RT1.1 RV1.1 | length 22.6
  Top Layer w0.635: RT1.1@141.478,115.891 137.668,112.081 137.668,106.426 144.713,99.381 144.713,99.036 144.763,98.986 R46.2@145.923,98.986
EARTH: C2.1 C3.1 C13.2 C14.2 J2.3 pad.0@157.988,110.858
GND-P: C1.2 C4.2 C5.2 C6.2 C8.2 C9.2 C10.2 C15.2 C16.2 C17.2 C19.2 C20.2 C21.2 C22.2 C23.2 C24.2 C26.2 C31.2 C32.2 C33.1 C36.2 C37.2 C38.2 C39.2 C40.2 C41.2 C42.2 D10.2 HS1.2 J1.3 J1.4 Q1.3 Q2.3 R3.1 R4.1 R5.2 R6.2 R8.2 R12.1 R16.1 R27.1 R34.1 R43.1 T1.11 TP6.1 U1.2 U1.4 U2.2 U2.4 U3.1 U4.3 U5.3 U6.6 U9.3 | length 78
  Top Layer w0.305: 164.338,58.166 164.398,58.226 ; C33.1@164.757,63.881 164.757,62.027 C36.2@164.808,61.976 C36.2@164.973,61.811
  Top Layer w0.381: 164.398,58.226 U6.6@164.398,59.268 164.398,60.676 164.973,61.251 C36.2@164.973,61.811
  Top Layer w0.508: 164.338,58.166 164.973,57.531 167.099,57.531 C39.2@167.264,57.696 R27.1@169.169,57.696
  Top Layer w1.27: C15.2@19.558,86.286 v1(19.558,92.456)
  Bottom Layer w1.27: HS1.2@19.309,120.904 16.891,120.904 10.668,114.681 10.668,96.901 15.113,92.456 v1(19.558,92.456) 30.988,92.456 ; TP6.1@53.848,83.566 56.388,83.566 57.658,84.836 61.854,84.836 Q1.3@62.489,84.201
  other v1: 165.608,48.641 169.418,48.641 171.958,48.641 174.498,48.641 162.433,50.546 165.608,50.546 171.958,51.181 178.943,51.181 174.571,51.396 160.528,51.816 165.608,52.451 156.718,53.086 158.623,53.086 174.498,53.615 171.958,53.721 178.943,53.721 156.718,54.991 158.623,54.991 161.798,54.991 184.658,55.372 188.468,55.471 51.943,56.261 61.468,56.261 63.373,56.261 189.738,56.896 29.083,57.531 32.893,57.531 36.068,57.531 162.209,57.531 61.468,58.166 63.373,58.166 69.723,58.166 182.626,58.42 185.42,58.42 51.943,58.801 67.818,60.071 29.083,60.706 32.893,60.706 36.068,60.706 45.593,60.706 40.513,61.976 43.053,61.976 67.818,61.976 189.738,63.246 27.813,64.516 157.353,65.151 159.893,65.151 189.738,65.786 182.372,66.294 159.893,67.691 162.433,67.691 31.623,68.326 174.498,68.326 180.848,68.961 184.023,68.961 45.212,69.088 48.514,69.088 165.1,69.088 27.813,69.596 159.893,70.231 51.816,71.247 57.15,71.247 59.944,71.247 180.848,71.501 184.023,71.501 65.278,71.628 48.768,71.882 31.623,73.406 27.813,74.041 62.103,74.676 64.008,74.676 46.228,75.311 49.403,75.311 37.338,77.216 46.228,77.851 49.403,77.851 51.943,77.851 62.103,77.851 64.008,77.851 31.623,78.486 36.068,79.121 38.608,79.121 51.308,97.536 53.213,97.536 55.118,97.536 57.023,97.536 58.928,97.536 60.833,97.536 62.738,97.536 64.643,97.536 66.548,97.536 68.453,97.536
  other v2: 185.42,18.796 182.88,21.082 185.42,21.082 187.96,21.082 51.816,65.786 51.816,67.564
  other v3: 180.533,49.3 181.991,50.643
GND-S: C18.1 C28.2 C29.2 C30.2 J5.2 J5.4 J5.6 J5.8 Q3.2 R15.1 R35.2 T1.4 T1.6 TP10.1 U4.2 U7.3 U8.3 | length 222.4
  Top Layer w0.635: v2(136.398,142.621) 137.85,142.621 C18.1@138.31,143.081 R15.1@138.31,141.303 ; Q3.2@138.033,138.951 R15.1@138.033,140.861 ; U7.3@209.509,56.955 212.434,56.955 R35.2@212.684,57.205
  Bottom Layer w0.635: v2(136.398,142.621) 137.033,143.256 145.923,143.256 150.495,147.828 256.286,147.828 260.223,143.891 260.223,86.106 251.968,77.851 235.862,77.851 235.781,77.769
  other v1: 213.36,30.988 213.36,34.036 213.36,36.83 205.994,52.832 208.788,52.832 211.582,52.832 214.884,52.832 216.154,54.864 218.694,54.864 202.946,55.372 210.971,56.955 207.518,57.658 216.154,57.658 218.694,57.658 202.946,58.166 206.756,59.944 204.216,62.738 211.582,66.548 205.232,66.802 208.28,66.802 207.518,68.834 210.312,68.834 212.852,68.834 203.454,78.232 203.454,80.772 203.454,83.058 203.454,85.344
  other v2: 204.47,19.304 222.25,24.638 227.584,24.638 231.394,24.638 211.074,25.146 227.33,32.512 231.394,32.512 231.394,38.608 227.584,42.672 209.042,45.212 213.36,45.212 232.41,47.498 227.584,49.276 232.41,54.356 220.98,63.246 223.012,67.564 223.012,72.898 226.314,72.898 226.314,75.946
INRUSH_RELAY: J5.3 R13.2 | length 246.7
  Top Layer w0.635: R13.2@143.212,143.081 148.213,148.082 256.032,148.082 260.223,143.891 260.223,82.931 238.76,61.468 238.76,51.105 222.707,35.052 J5.3@221.234,35.052
NetC2_2: C2.2 C12.1 L3.12 L4.1
NetC7_1: C7.1 D1.2 D3.1 D5.2 L1.1 TP1.1 | length 26.2
  Top Layer w1.27: D1.2@119.888,108.966 137.033,91.821 D5.2@137.033,89.916
NetC7_2: C7.2 D3.4 R5.1 R6.1 R7.2 R8.1 | length 53
  Top Layer w0.635: v1(39.878,72.136) 33.528,78.486 33.528,90.551 43.688,100.711 C7.2@47.069,100.711 ; R7.2@45.808,64.985 46.863,66.04 46.863,71.501 v1(46.228,72.136)
  Bottom Layer w0.635: v1(39.878,72.136) v1(46.228,72.136)
NetC11_1: C11.1 F1.3 F1.4 L3.1
NetC11_2: C11.2 L3.6 TP12.1
NetC12_2: C12.2 C13.1 L3.7 L4.6
NetC15_1: C15.1 HS3.1 | length 6.9
  Top Layer w1.27: HS3.1@19.309,76.581 19.558,76.83 C15.1@19.558,83.386
NetC16_1: C16.1 R7.1 U3.3 | length 7.4
  Top Layer w0.635: R7.1@45.72,63.208 C16.1@47.498,63.208 47.498,62.611 48.133,61.976 U3.3@52.218,61.976
NetC17_1: C17.1 U3.2 | length 2.5
  Top Layer w0.635: C17.1@49.703,63.246 U3.2@52.218,63.246
NetC18_2: C18.2 Q3.1 R13.1 R15.2 TP7.1 | length 14
  Top Layer w0.635: TP7.1@133.223,143.891 133.858,144.526 139.573,144.526 139.91,144.189 C18.2@139.91,143.081 ; R15.2@139.783,141.176 139.783,140.371 139.933,140.221 Q3.1@139.933,138.951 ; R15.2@139.91,141.303 C18.2@139.91,143.081 ; R13.1@141.612,143.081 C18.2@139.91,143.081
NetC21_1: C21.1 R9.2 R16.2 R48.2 U3.6 | length 63.7
  Top Layer w0.635: R48.2@21.882,50.546 65.278,50.546 67.564,52.832 67.564,55.552 R9.2@67.638,55.626 67.638,57.076 62.738,61.976 61.633,61.976 R16.2@61.468,62.141 59.802,62.141 C21.1@59.778,62.165 59.589,61.976 U3.6@57.018,61.976
NetC22_1: C22.1 R14.1 | length 4.4
  Top Layer w0.635: C22.1@56.703,56.261 58.293,56.261 58.928,56.896 58.928,58.715 R14.1@58.842,58.801
NetC23_1: C23.1 R14.2 U3.5 | length 3.8
  Top Layer w0.635: C23.1@55.418,58.801 57.242,58.801 57.242,60.482 U3.5@57.018,60.706
NetC24_1: C24.1 C25.1 R17.1 R18.2 RF1.1 T1.7
NetC25_2: C25.2 D6.1 R17.2
NetC27_1: C27.1 R23.2 | length 2.6
  Top Layer w1.27: R23.2@206.428,71.501 C27.1@209.042,71.501
NetC27_2: C27.2 C29.1 C30.1 D7.1 L6.1 R20.1
NetC31_1: C31.1 C33.2 D10.1 Q5.3 R22.1 R25.2 U6.8 | length 81.2
  Top Layer w0.381: 159.893,61.976 160.109,61.76 162.649,61.76 ; C33.2@162.649,63.881 162.649,61.76 ; U6.8@163.098,59.268 163.098,61.311 162.649,61.76
  Top Layer w0.635: v1(154.813,63.881) Q5.3@156.323,62.371 ; R22.1@176.403,62.431 176.426,62.431 177.876,63.881 180.149,63.881 181.483,62.547 ; C31.1@187.198,65.111 v1(187.198,71.501)
  Top Layer w1.27: Q5.3@156.443,62.371 159.498,62.371 159.893,61.976 R25.2@159.893,60.251 ; 181.483,62.547 183.325,62.547 185.928,65.151 187.158,65.151 C31.1@187.198,65.111
  Bottom Layer w0.635: v1(154.813,63.881) 154.178,63.881 152.273,65.786 152.273,71.501 154.178,73.406 164.338,73.406 166.243,71.501 173.863,71.501 175.133,72.771 185.928,72.771 v1(187.198,71.501)
NetC32_1: C32.1 D9.3 R22.2 | length 7.9
  Top Layer w0.635: D9.3@171.323,61.656 171.638,61.341 171.958,61.341 173.863,63.246 C32.1@173.863,64.986 174.968,64.986 175.313,65.331 R22.2@176.403,65.331
NetC34_1: C34.1 C35.1 U5.2 U7.2 | length 11.1
  Top Layer w0.508: U5.2@201.335,63.881 206.008,63.881 C35.1@206.804,63.085 206.804,62.436 208.06,61.18 C34.1@208.709,61.18 208.559,61.03 U7.2@208.559,59.055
